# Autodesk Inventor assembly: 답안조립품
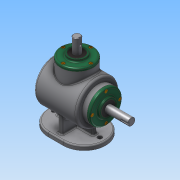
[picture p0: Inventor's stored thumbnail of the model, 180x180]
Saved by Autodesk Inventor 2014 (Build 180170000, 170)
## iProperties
Created: 2016-04
Part Number: 답안조립품
Document SubType Name: Assembly
Designer: 601-
Author: 601-
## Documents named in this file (14)
- D:\460408V1012\답안조립품.iam
- D:\460408V1012\본체.ipt
- D:\460408V1012\메인 축.ipt
- 메인 축.ipt
- D:\460408V1012\키 5x5.ipt
- D:\460408V1012\메인 베벨기어.ipt
- D:\460408V1012\베어링 6203.ipt
- D:\460408V1012\커버.ipt
- D:\460408V1012\오일실 17 32 8.ipt
- D:\460408V1012\서브 축.ipt
- 서브 축.ipt
- D:\460408V1012\키 4x4.ipt
- D:\460408V1012\서브 베벨기어.ipt
- D:\460408V1012\M4.ipt
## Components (8 placed, 1 different names)
1. M4:2
2. M4:3
3. M4:4
4. M4:5
5. M4:1
6. M4:6
7. M4:7
8. M4:8
